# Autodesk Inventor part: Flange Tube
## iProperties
Shininess: 64.0
Length Units: 11272
Angle Units: 11279
Time Units: 11290
Mass Units: 11286
Length Display Precision: 3
Angle Display Precision: 2
Compacted: True
Part Number: Flange Tube
Document SubType Name: Modeling
Created: 2004-06
Designer: jpittman
Manufacturer: Standard
Standards Organization: Custom
Density: 0.0
Volumn: 0.0
Area: 0.0
PropertySet Name: Model Information
Control State: 0
Master: False
Checked Out: False
Author: jpittman
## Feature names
1. Extrusion1
